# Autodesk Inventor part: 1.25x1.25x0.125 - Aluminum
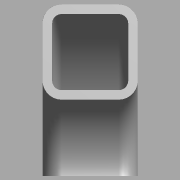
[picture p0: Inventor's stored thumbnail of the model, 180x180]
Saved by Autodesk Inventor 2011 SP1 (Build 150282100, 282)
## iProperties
Created: 2011-03
Part Number: 1.25x1.25x0.125 - Aluminum
Material: Default
Document SubType Name: Modeling
Designer: bamfomg
Density: 1 g/cm^3
Author: bamfomg
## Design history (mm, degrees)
derived "Square Tube Corners.ipt" dims "d2" = 15.875, "d3" = 15.875, "d6" = 3.175, "d7" = 3.175, "d8" = 3.175, "d12" = 90 deg, "d16" = 1.5875, "d18" = 30 deg, "ID_Rad" = 3.175, "OD_Rad" = 6.35, "Side_One" = 31.75, "Side_Two" = 31.75, "Thickness" = 3.175, "Bend_IDRad" = 25.4, "Bevel_Angl" = 30 deg, "Bevel_Dist" = 1.5875
body "Solid1"
feature "Solid1::Square Tube Corners.ipt" dims "d2" = 15.875, "d3" = 15.875, "d6" = 3.175, "d7" = 3.175, "d8" = 3.175, "d12" = 90 deg, "d16" = 1.5875, "d18" = 30 deg, "ID_Rad" = 3.175, "OD_Rad" = 6.35, "Side_One" = 31.75, "Side_Two" = 31.75, "Thickness" = 3.175, "Bend_IDRad" = 25.4, "Bevel_Angl" = 30 deg, "Bevel_Dist" = 1.5875, "ScaleForDerivedMember" = 10
tag "TaggingFeature1"
